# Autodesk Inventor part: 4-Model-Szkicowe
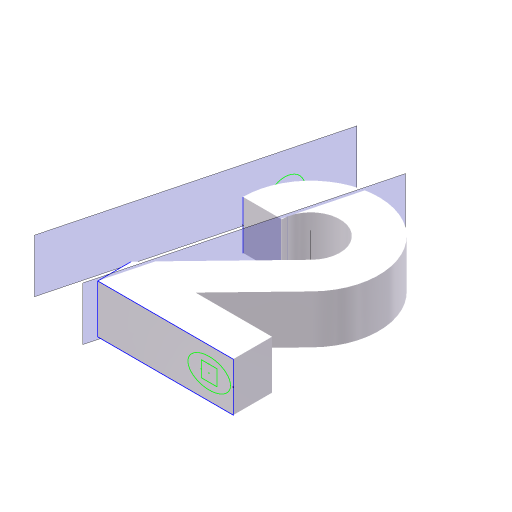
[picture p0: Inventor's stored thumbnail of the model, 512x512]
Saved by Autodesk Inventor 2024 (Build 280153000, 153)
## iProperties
Company: ATC
Created: 2023-03
Part Number: 4-Model-Szkicowe
Document SubType Name: Modeling
Designer: Andrzej Jaskulski
Density: 1 g/cm^3
Material: Kurs-AJ
Appearance: Kurs-AJ
Checked By: A.J.
Engr Approved By: Andrzej Jaskulski
Mfg Approved By: Andrzej Jaskulski
Authority: A.J.
Title: A.J.: Kurs R2024-MEP
Author: Andrzej Jaskulski
Revision Number: 1/24
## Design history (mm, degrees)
sketch "Zarys dwójki"
  geometry: L1 (0, 0)-(140, 0); L2 (140, 0)-(140, 40); L3 (140, 40)-(61.086, 40); L4 (0, 0)-(0, 34.326); L5 (0, 34.326)-(91.58, 129.16); L6 (61.086, 40)-(120.354, 101.374); L7 (40, 150)-(0, 150); A1 r 30 centre (70, 150) between (91.58, 129.16) and (40, 150); A2 r 70 centre (70, 150) between (120.354, 101.374) and (0, 150)
  constraints: 14 end point, 4 point on circle, 3 perpendicular, 2 centre point, 2 parallel, 2 tangent, 1 coincident, 1 horizontal, 1 point on line, 1 other
  dimensions: "d0" = 140 distance of L1.start L1.end; "d1" = 150 distance from line of A1.centre L1; "d2" = 70 radius of A2; "d3" = 30 radius of A1; "d4" = 70 distance from line of L4 A1.centre; "d5" = 46 deg angle of L6 L3; "d6" = 40 distance of L1.end L2.end
extrude "Dwójka" new body sketch "Zarys dwójki" distance "d7" = 50; taper "d8" = 0 deg
node "Odsunięta od Stycznej do Walca"
  node "Styczna do Walca"
node "Oś powierzchni walcowej"
sketch "Elipsa i Kwadrat"
  geometry: L1 (140, 0)-(140, 50) reference; L2 (106.938, 16.938)-(123.062, 16.938); L3 (123.062, 16.938)-(123.062, 33.062); L4 (123.062, 33.062)-(106.938, 33.062); L5 (106.938, 33.062)-(106.938, 16.938); L6 (140, 50)-(0, 50) reference; L7 (0, 0)-(0, 50) reference; L8 (0, 0)-(140, 0) reference; 4 further points; 1 other entity
  constraints: 8 end point, 3 midpoint, 2 horizontal alignment, 2 parallel, 2 perpendicular, 1 horizontal, 1 vertical alignment, 2 other
sketch "Okręgi"
  geometry: L1 (50, 0)-(50, 34.326) reference; L2 (0, 34.326)-(50, 34.326) reference; L3 (0, 34.326)-(0, 0) reference; L4 (0, 0)-(50, 0) reference; L5 (0, 150)-(50, 150) reference; C1 r 12 at (25, 193); C2 r 21.5 at (25, 193); 1 further point
  constraints: 2 centre point, 1 coincident, 1 midpoint, 1 vertical alignment
node "Bryła1"
node "Korpusy bryłowe"
node "Korpusy powierzchniowe"
other parameters: "d5" = 46 deg
